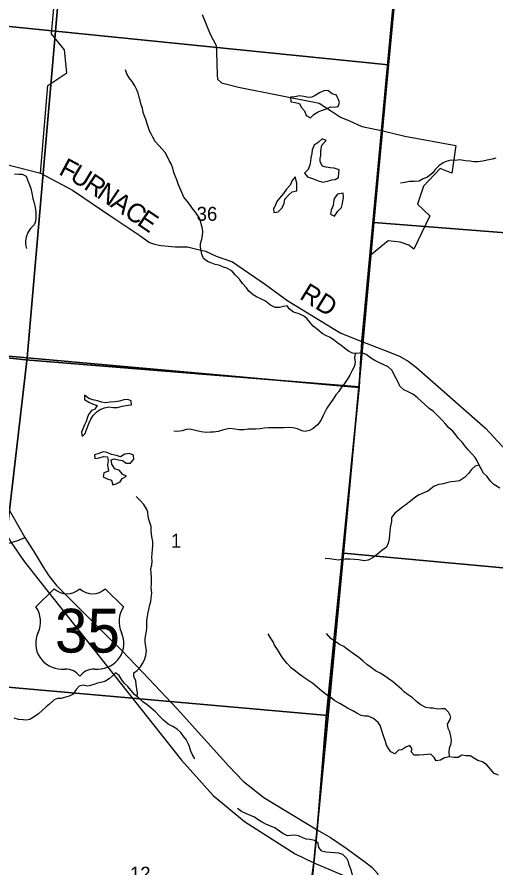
# Model space of a CAD drawing. Extents: x 1715311 to 2083412, y 146837 to 553079.
# Drawn here: x 1947566 to 1955162, y 364200 to 377700 of the extents above; entities that cross this region are included whole.
import ezdxf

# ---------------------------------------------------------------- set-up
doc = ezdxf.new("R2010")
doc.units = 0
for name, color, linetype in [('GM_X_County_Road', 7, 'Continuous'), ('GM_X_County_Road_Text', 7, 'Continuous'), ('GM_X_Minor_Lake', 7, 'Continuous'), ('GM_X_Minor_River', 7, 'Continuous'), ('GM_X_Section', 7, 'Continuous'), ('GM_X_Section_Text', 7, 'Continuous'), ('GM_X_Township', 7, 'Continuous'), ('GM_X_Township_Road', 7, 'Continuous'), ('GM_X_Township_ROW', 7, 'Continuous'), ('GM_X_US_Location', 7, 'Continuous'), ('GM_X_US_Route', 7, 'Continuous'), ('GM_X_US_Shield', 7, 'Continuous')]:
    doc.layers.add(name, color=color, linetype=linetype)

msp = doc.modelspace()

# ---------------------------------------------------------------- linework, layer by layer
at = {"layer": 'GM_X_County_Road'}
for points in [[(1947381, 375360), (1947938, 375218), (1948449, 374950), (1949089, 374513), (1949517, 374227), (1949672, 374116), (1949751, 374093), (1949854, 374070), (1950082, 374047), (1950276, 374047), (1950424, 374013), (1950561, 373979), (1950732, 373899), (1950989, 373810), (1951517, 373452), (1951872, 373193), (1952710, 372678), (1953044, 372548)], [(1953044, 372548), (1953047, 372547), (1953416, 372405), (1953643, 372314), (1953784, 372236), (1953917, 372131), (1955010, 371167), (1955480, 370665), (1955907, 370295), (1956132, 370050), (1956314, 369854), (1956364, 369820), (1956441, 369785), (1956595, 369722), (1956724, 369733), (1957024, 369656), (1958038, 369355), (1958352, 369271), (1958562, 369250), (1959149, 369313), (1960065, 369419), (1960664, 369399), (1961250, 369383)], [(1947423, 369907), (1947692, 369431), (1947849, 369186), (1947979, 368974), (1948070, 368825), (1948194, 368673), (1948430, 368430), (1948605, 368259), (1948936, 367927), (1949230, 367637), (1949664, 367181), (1950110, 366714), (1950544, 366231), (1950935, 365802), (1951161, 365561), (1951491, 365304), (1952338, 364791), (1952549, 364669), (1952813, 364487)], [(1946977, 369315), (1947054, 369303), (1947208, 369291), (1947288, 369299), (1947475, 369355), (1947578, 369384), (1947692, 369431)], [(1952813, 364487), (1952819, 364483), (1953091, 364287), (1953211, 364192), (1953293, 364094), (1953318, 364008), (1953330, 363947), (1953324, 363824)]]:
    msp.add_lwpolyline(points, dxfattribs=at)
at = {"layer": 'GM_X_Minor_Lake'}
for points in [[(1952656, 376434), (1952645, 376456), (1952577, 376482), (1952506, 376535), (1952440, 376529), (1952376, 376495), (1952302, 376455), (1952252, 376429), (1952196, 376422), (1952126, 376438), (1952056, 376446), (1951982, 376434), (1951914, 376428)], [(1951914, 376428), (1951916, 376350), (1951988, 376342), (1952055, 376324), (1952081, 376270), (1952135, 376208), (1952159, 376137), (1952230, 376099), (1952289, 376157), (1952351, 376195), (1952407, 376213), (1952471, 376234), (1952547, 376272), (1952617, 376270), (1952669, 376278), (1952689, 376340), (1952677, 376390), (1952656, 376434)], [(1952479, 375736), (1952415, 375766), (1952353, 375708), (1952287, 375664), (1952255, 375588), (1952249, 375530), (1952236, 375462), (1952232, 375412), (1952222, 375346), (1952192, 375278), (1952136, 375220), (1952185, 375160), (1952245, 375140), (1952315, 375116), (1952369, 375094), (1952393, 375086)], [(1952393, 375086), (1952423, 375077), (1952501, 375091), (1952567, 375111), (1952623, 375119), (1952677, 375153), (1952683, 375225), (1952685, 375275), (1952609, 375297), (1952543, 375303), (1952480, 375315), (1952420, 375332), (1952384, 375398), (1952384, 375450), (1952392, 375502), (1952396, 375558), (1952401, 375608), (1952413, 375664), (1952479, 375736)], [(1951989, 375159), (1951937, 375101), (1951909, 375029), (1951849, 374963), (1951799, 374895), (1951737, 374823), (1951698, 374767), (1951674, 374715), (1951644, 374649), (1951646, 374597), (1951690, 374601)], [(1951690, 374601), (1951714, 374603), (1951780, 374667), (1951810, 374741), (1951822, 374807), (1951881, 374869), (1951941, 374921), (1952011, 374941), (1952011, 375059), (1951989, 375159)], [(1952752, 374902), (1952658, 374886), (1952604, 374819), (1952596, 374760), (1952593, 374704), (1952561, 374634), (1952549, 374568), (1952592, 374548)], [(1952592, 374548), (1952613, 374538), (1952667, 374614), (1952725, 374674), (1952741, 374740), (1952754, 374840), (1952752, 374902)], [(1949386, 371541), (1949382, 371605), (1949330, 371627), (1949262, 371622), (1949194, 371600), (1949120, 371590), (1949046, 371584), (1948976, 371574), (1948910, 371581), (1948846, 371605), (1948771, 371621), (1948709, 371641), (1948641, 371694), (1948639, 371624), (1948710, 371583), (1948776, 371551), (1948838, 371531), (1948820, 371497)], [(1948820, 371497), (1948806, 371473), (1948752, 371449), (1948704, 371387), (1948680, 371329), (1948665, 371277), (1948639, 371225), (1948619, 371171), (1948589, 371105), (1948601, 371037), (1948651, 371083), (1948667, 371135), (1948693, 371201), (1948711, 371253), (1948738, 371313), (1948778, 371373), (1948838, 371433), (1948888, 371465), (1948956, 371494), (1949024, 371510), (1949094, 371500), (1949166, 371496), (1949236, 371521), (1949302, 371527), (1949386, 371541)], [(1949148, 370515), (1949120, 370525), (1949071, 370597), (1949061, 370665), (1949113, 370683), (1949181, 370667), (1949243, 370654), (1949299, 370614), (1949369, 370612), (1949421, 370676), (1949419, 370740), (1949353, 370768), (1949279, 370754), (1949211, 370713), (1949149, 370735), (1949069, 370753), (1948999, 370783), (1948934, 370796), (1948866, 370768), (1948800, 370746), (1948801, 370690), (1948871, 370700), (1948939, 370718), (1949007, 370713), (1949013, 370649), (1949007, 370589), (1949020, 370489)], [(1949020, 370489), (1948948, 370459), (1948934, 370395), (1949000, 370363), (1949066, 370341), (1949090, 370270), (1949144, 370284), (1949206, 370318), (1949238, 370370), (1949304, 370408), (1949248, 370434), (1949188, 370500), (1949148, 370515)]]:
    msp.add_lwpolyline(points, dxfattribs=at)
at = {"layer": 'GM_X_Minor_River'}
for points in [[(1951737, 373085), (1951667, 373088), (1951595, 373122), (1951513, 373188), (1951439, 373226), (1951372, 373255), (1951320, 373289), (1951252, 373347), (1951212, 373397), (1951148, 373466), (1951103, 373534), (1951041, 373602), (1950981, 373668), (1950902, 373709), (1950846, 373727), (1950774, 373757), (1950718, 373771), (1950664, 373790), (1950594, 373818), (1950532, 373866), (1950501, 373934), (1950491, 373984), (1950483, 374044), (1950483, 374102), (1950502, 374170), (1950516, 374229), (1950518, 374289), (1950514, 374341), (1950500, 374393), (1950483, 374465), (1950459, 374517), (1950413, 374585), (1950357, 374658), (1950306, 374726), (1950268, 374776), (1950220, 374840), (1950184, 374914), (1950155, 374985), (1950135, 375035), (1950107, 375111), (1950079, 375179), (1950056, 375229), (1950042, 375301), (1950014, 375367), (1949986, 375418), (1949955, 375488), (1949919, 375548), (1949875, 375600), (1949819, 375660), (1949760, 375723), (1949726, 375793), (1949698, 375843), (1949674, 375893), (1949651, 375953), (1949635, 376003), (1949617, 376063), (1949591, 376126), (1949573, 376182), (1949558, 376250), (1949542, 376306), (1949524, 376376), (1949510, 376428), (1949493, 376492), (1949463, 376551), (1949439, 376605), (1949395, 376673), (1949347, 376735), (1949314, 376799), (1949292, 376859)], [(1955173, 375459), (1955117, 375443), (1955039, 375425), (1954967, 375412), (1954884, 375398), (1954828, 375402), (1954760, 375410), (1954688, 375416), (1954606, 375433), (1954528, 375421), (1954458, 375425), (1954388, 375403), (1954338, 375382), (1954268, 375338), (1954210, 375276), (1954176, 375224), (1954091, 375158), (1954021, 375128), (1953957, 375092), (1953885, 375089), (1953805, 375089), (1953731, 375071), (1953660, 375059)], [(1947524, 375207), (1947598, 375203), (1947650, 375203), (1947710, 375171), (1947741, 375098), (1947767, 375036), (1947785, 374976), (1947801, 374902), (1947820, 374816), (1947834, 374764), (1947850, 374700), (1947860, 374644), (1947866, 374593), (1947867, 374517), (1947861, 374453), (1947841, 374401), (1947779, 374343), (1947739, 374278), (1947714, 374204), (1947702, 374146)], [(1947702, 374146), (1947704, 374089), (1947716, 374021)], [(1955241, 370217), (1955146, 370275), (1955088, 370333), (1955040, 370400), (1954980, 370454), (1954941, 370522), (1954915, 370572), (1954877, 370652), (1954845, 370703), (1954800, 370757), (1954738, 370827), (1954684, 370889), (1954638, 370946), (1954579, 371008), (1954539, 371066), (1954491, 371120), (1954431, 371173), (1954372, 371241), (1954324, 371297), (1954260, 371359), (1954184, 371432), (1954115, 371482), (1954043, 371548), (1953989, 371598), (1953926, 371655), (1953858, 371709), (1953784, 371747), (1953714, 371776), (1953652, 371834), (1953623, 371902), (1953591, 371956), (1953523, 372092), (1953466, 372145), (1953386, 372183), (1953326, 372205), (1953252, 372244), (1953182, 372288), (1953113, 372338), (1953045, 372368), (1952965, 372355), (1952899, 372361), (1952833, 372391), (1952773, 372441), (1952720, 372482), (1952666, 372520), (1952614, 372560), (1952542, 372608), (1952474, 372640), (1952415, 372675), (1952343, 372737), (1952273, 372789), (1952219, 372852), (1952170, 372910), (1952118, 372954), (1952036, 372988), (1951960, 373013), (1951890, 373065), (1951857, 373115), (1951799, 373103), (1951737, 373085)], [(1952941, 372357), (1952931, 372283), (1952940, 372221), (1952928, 372154), (1952894, 372085), (1952854, 372013), (1952814, 371945), (1952759, 371863), (1952711, 371807), (1952681, 371753), (1952635, 371701), (1952589, 371629), (1952539, 371555), (1952492, 371489), (1952458, 371423), (1952434, 371371), (1952394, 371293), (1952344, 371223), (1952273, 371163), (1952217, 371130), (1952147, 371114), (1952095, 371128), (1952022, 371158), (1951948, 371174), (1951880, 371179), (1951810, 371173), (1951752, 371173), (1951696, 371175), (1951626, 371176), (1951566, 371174), (1951492, 371168), (1951428, 371160), (1951362, 371152), (1951296, 371153), (1951244, 371151), (1951172, 371145), (1951095, 371145), (1951027, 371153), (1950949, 371162), (1950893, 371154), (1950831, 371138), (1950761, 371118), (1950691, 371106), (1950639, 371105), (1950573, 371103), (1950493, 371111), (1950425, 371127), (1950359, 371145), (1950307, 371154), (1950255, 371150), (1950189, 371128), (1950123, 371118), (1950060, 371124)], [(1954909, 370584), (1954847, 370566), (1954791, 370515), (1954743, 370451), (1954676, 370385), (1954598, 370333), (1954522, 370321), (1954468, 370315), (1954412, 370308), (1954342, 370284), (1954268, 370276), (1954196, 370246), (1954144, 370206), (1954094, 370168), (1954030, 370141), (1953956, 370109), (1953906, 370081), (1953846, 370031), (1953796, 369995), (1953746, 369953), (1953696, 369921), (1953638, 369870), (1953570, 369822), (1953515, 369750), (1953515, 369688), (1953507, 369638), (1953495, 369588), (1953491, 369534), (1953486, 369478), (1953480, 369412), (1953464, 369342), (1953436, 369278), (1953364, 369228), (1953290, 369162), (1953225, 369116), (1953149, 369072), (1953085, 369060), (1952998, 369079), (1952928, 369081), (1952854, 369087), (1952784, 369087), (1952726, 369084), (1952674, 369074), (1952604, 369084), (1952532, 369096), (1952466, 369098)], [(1949476, 366902), (1949482, 366963), (1949470, 367030), (1949462, 367100), (1949455, 367154), (1949425, 367224), (1949425, 367286), (1949475, 367322), (1949527, 367380), (1949559, 367432), (1949590, 367492), (1949614, 367558), (1949626, 367632), (1949614, 367700), (1949603, 367772), (1949603, 367824), (1949615, 367892), (1949623, 367944), (1949627, 367998), (1949632, 368066), (1949632, 368120), (1949638, 368176), (1949650, 368240), (1949660, 368290), (1949676, 368362), (1949691, 368418), (1949699, 368470), (1949709, 368553), (1949699, 368633), (1949702, 368689), (1949702, 368741), (1949702, 368795), (1949698, 368865), (1949694, 368941), (1949709, 368995), (1949715, 369063), (1949711, 369113), (1949715, 369177), (1949719, 369243), (1949724, 369301), (1949724, 369369), (1949716, 369424), (1949704, 369480), (1949699, 369552), (1949697, 369606), (1949683, 369656), (1949659, 369720), (1949649, 369774), (1949644, 369834), (1949624, 369886), (1949584, 369959), (1949524, 370021), (1949461, 370085)], [(1951772, 367547), (1951738, 367601), (1951706, 367655), (1951660, 367721), (1951636, 367774), (1951597, 367842), (1951557, 367902)], [(1954439, 365948), (1954432, 366021), (1954440, 366089), (1954466, 366159), (1954470, 366213), (1954463, 366279), (1954445, 366349), (1954417, 366399), (1954405, 366467), (1954443, 366533), (1954460, 366587), (1954424, 366661), (1954368, 366710), (1954316, 366712), (1954248, 366706), (1954182, 366722), (1954130, 366724), (1954064, 366733), (1953973, 366783), (1953917, 366829), (1953845, 366891), (1953785, 366936), (1953726, 366978), (1953674, 367024), (1953602, 367089), (1953532, 367145), (1953465, 367193), (1953405, 367237), (1953339, 367276), (1953265, 367316), (1953195, 367366), (1953124, 367418), (1953068, 367467), (1952998, 367529), (1952946, 367565), (1952893, 367603), (1952815, 367662), (1952759, 367702), (1952693, 367734), (1952621, 367782), (1952552, 367831), (1952482, 367909)], [(1955218, 365656), (1955150, 365686), (1955092, 365756), (1955034, 365820), (1954965, 365871), (1954891, 365893), (1954839, 365923), (1954767, 365967), (1954701, 365966), (1954633, 365978), (1954577, 365940), (1954509, 365938), (1954439, 365948), (1954361, 365933), (1954295, 365897), (1954229, 365885), (1954198, 365939), (1954142, 365993), (1954086, 365986), (1954030, 365982), (1953950, 365978), (1953878, 365976), (1953832, 366027), (1953846, 366077), (1953811, 366129), (1953743, 366101), (1953681, 366063), (1953629, 366053), (1953568, 365999), (1953509, 366030), (1953471, 366082), (1953439, 366134), (1953423, 366194), (1953395, 366268), (1953374, 366332), (1953358, 366382), (1953336, 366445), (1953306, 366495), (1953229, 366559), (1953145, 366595), (1953091, 366594), (1953035, 366608), (1952969, 366642), (1952905, 366680), (1952818, 366723), (1952750, 366765), (1952696, 366799), (1952618, 366839), (1952554, 366890), (1952485, 366932), (1952411, 366992), (1952335, 367057), (1952270, 367115), (1952206, 367157), (1952124, 367209), (1952050, 367260), (1951992, 367310), (1951929, 367360), (1951859, 367432), (1951807, 367497), (1951772, 367547)], [(1950393, 365915), (1950354, 365979), (1950330, 366042), (1950306, 366112), (1950286, 366162), (1950255, 366226), (1950209, 366284), (1950171, 366334), (1950113, 366387), (1950045, 366433), (1949966, 366467), (1949894, 366530), (1949828, 366602), (1949767, 366664), (1949701, 366724), (1949633, 366773), (1949567, 366825), (1949500, 366881), (1949432, 366940), (1949376, 367006), (1949330, 367068), (1949269, 367122), (1949219, 367190), (1949191, 367241), (1949131, 367283), (1949079, 367231), (1949029, 367189), (1948963, 367147), (1948897, 367129), (1948843, 367118), (1948787, 367098), (1948733, 367082), (1948681, 367074), (1948617, 367086), (1948553, 367074), (1948507, 367017), (1948459, 366945), (1948393, 366911), (1948323, 366893), (1948263, 366877), (1948209, 366875), (1948159, 366857), (1948085, 366786), (1948029, 366742), (1947974, 366690), (1947906, 366632), (1947840, 366586), (1947768, 366540), (1947714, 366531), (1947662, 366535), (1947592, 366541), (1947522, 366565)], [(1952845, 364228), (1952835, 364284), (1952809, 364336), (1952742, 364398), (1952678, 364422), (1952614, 364425), (1952542, 364429), (1952476, 364433), (1952410, 364453), (1952364, 364509), (1952353, 364578), (1952295, 364622), (1952223, 364634), (1952161, 364642), (1952109, 364662), (1952039, 364695), (1951984, 364703), (1951916, 364699), (1951864, 364697), (1951792, 364734), (1951738, 364768), (1951666, 364820), (1951596, 364848), (1951523, 364879), (1951453, 364915), (1951401, 364951), (1951341, 364989), (1951275, 365019), (1951204, 365048), (1951136, 365082), (1951072, 365128)], [(1952845, 364228), (1952873, 364156), (1952885, 364096), (1952905, 364006), (1952918, 363942), (1952922, 363866), (1952904, 363792), (1952865, 363716), (1952811, 363644), (1952733, 363581), (1952663, 363539), (1952599, 363513), (1952549, 363487), (1952497, 363464), (1952421, 363430), (1952353, 363414), (1952253, 363433)]]:
    msp.add_lwpolyline(points, dxfattribs=at)
at = {"layer": 'GM_X_Section'}
for points in [[(1943359, 383370), (1948626, 382716), (1948176, 377474), (1942934, 378008)], [(1948626, 382716), (1953956, 382183), (1953734, 379717), (1953472, 376942), (1948176, 377474)], [(1959343, 379221), (1960259, 379152), (1959801, 373922), (1953239, 374434), (1953472, 376942), (1953734, 379717)], [(1942934, 378008), (1948176, 377474), (1947726, 372288), (1942460, 372757)], [(1953472, 376942), (1953239, 374434), (1952999, 371814), (1947726, 372288), (1948176, 377474)], [(1953239, 374434), (1959801, 373922), (1959375, 368573), (1952755, 369184), (1952999, 371814)], [(1942218, 372775), (1942460, 372757), (1947726, 372288), (1947119, 367081), (1941670, 367521)], [(1952999, 371814), (1952755, 369184), (1952509, 366608), (1947119, 367081), (1947726, 372288)], [(1952755, 369184), (1959375, 368573), (1958975, 363158), (1952234, 363778), (1952509, 366608)], [(1947119, 367081), (1952509, 366608), (1952234, 363778), (1951966, 361232), (1946510, 361726)]]:
    msp.add_lwpolyline(points, close=True, dxfattribs=at)
at = {"layer": 'GM_X_Township'}
for points in [[(1953709, 379667), (1953358, 375895), (1953174, 373907), (1953116, 373283), (1953047, 372547), (1953006, 371824), (1947703, 372256), (1945917, 372448), (1945530, 372486), (1942423, 372721), (1942174, 372734), (1937122, 373218)], [(1967018, 346390), (1960706, 346900), (1959377, 347007), (1957731, 347103), (1954890, 347384), (1950619, 347731), (1950869, 350176), (1950967, 351173), (1951154, 353065), (1951378, 355527), (1951408, 355623), (1951672, 358399), (1952102, 362654), (1952229, 363880), (1952285, 364266), (1952338, 364791), (1952480, 366566), (1953006, 371824), (1953047, 372547), (1953116, 373283), (1953174, 373907), (1953358, 375895), (1953709, 379667)], [(1937122, 373218), (1942174, 372734), (1942423, 372721), (1945530, 372486), (1945917, 372448), (1947703, 372256), (1953006, 371824), (1952480, 366566), (1952338, 364791), (1952285, 364266), (1952229, 363880)]]:
    msp.add_lwpolyline(points, dxfattribs=at)
at = {"layer": 'GM_X_Township_Road'}
for points in [[(1947938, 375218), (1948057, 376611), (1948358, 376812), (1948320, 377177), (1948115, 377435), (1948202, 378426), (1947646, 379472), (1947651, 379838)], [(1950507, 377740), (1950634, 377427), (1950733, 377247), (1950739, 377149), (1950746, 376782), (1950755, 376712), (1950815, 376655), (1950900, 376632), (1951088, 376586), (1952366, 376329), (1952579, 376193), (1952708, 376109), (1952850, 376051), (1953038, 375968)]]:
    msp.add_lwpolyline(points, dxfattribs=at)
at = {"layer": 'GM_X_Township_ROW'}
msp.add_lwpolyline([(1953038, 375968), (1953070, 375954), (1953358, 375895), (1953728, 375806), (1954542, 375657), (1954477, 375218), (1954290, 375296), (1954025, 375012), (1953929, 374728), (1954129, 374540), (1953873, 374013), (1953793, 374075), (1953657, 374121), (1953464, 374146), (1953174, 373907), (1953116, 373283), (1953047, 372547)], dxfattribs=at)
at = {"layer": 'GM_X_US_Route'}
msp.add_lwpolyline([(1947345, 369589), (1947475, 369355), (1947671, 369066), (1947941, 368724), (1950180, 365894), (1950683, 365335), (1951182, 364922), (1951987, 364408), (1952285, 364266), (1953324, 363824), (1953596, 363707)], dxfattribs=at)
at = {"layer": 'GM_X_US_Shield'}
for p, q in [((1948158, 368620), (1947868, 368330)), ((1949260, 368330), (1948970, 368620)), ((1948274, 367344), (1948332, 367344)), ((1948796, 367344), (1948854, 367344))]:
    msp.add_line(p, q, dxfattribs=at)
for centre, radius, start, end in [((1948361, 368827), 290, 225.573, 314.427), ((1948767, 368827), 290, 225.573, 314.427), ((1947535, 368097), 406, 334.5471, 35.0009), ((1949593, 368097), 406, 144.9991, 205.4529), ((1948269, 367750), 406, 154.8319, 270.6383), ((1948858, 367750), 406, 269.3617, 25.1681), ((1948332, 367054), 290, 36.8699, 90), ((1948796, 367054), 290, 90, 143.1301)]:
    msp.add_arc(centre, radius, start, end, dxfattribs=at)

# ---------------------------------------------------------------- texts
at = {"layer": 'GM_X_County_Road_Text'}
for s, rotation, p in [('F', 331.7581, (1948214, 375209)), ('U', 328.9781, (1948389, 375115)), ('R', 326.2071, (1948612, 374981)), ('N', 325.8573, (1948816, 374845)), ('A', 325.8553, (1949035, 374696)), ('C', 325.8553, (1949253, 374548)), ('E', 325.8559, (1949457, 374410)), ('RD', 328.3606, (1952040, 373234))]:
    msp.add_text(s, height=300, rotation=rotation, dxfattribs=at).set_placement(p)
at = {"layer": 'GM_X_Section_Text'}
for s, p in [('36', (1950421, 374463)), ('1', (1950011, 369271)), ('12', (1949360, 363983))]:
    msp.add_text(s, height=221, rotation=0, dxfattribs=at).set_placement(p)
at = {"layer": 'GM_X_US_Location'}
for s in ['/', '0']:
    msp.add_text(s, height=1, dxfattribs=at).set_placement((1948563, 367948))
msp.add_text('35', height=1, rotation=0, dxfattribs=at).set_placement((1948357, 367741))
at = {"layer": 'GM_X_US_Shield'}
msp.add_text('35', height=696.1, dxfattribs=at).set_placement((1948168, 367605))

doc.saveas('drawing.dxf')
